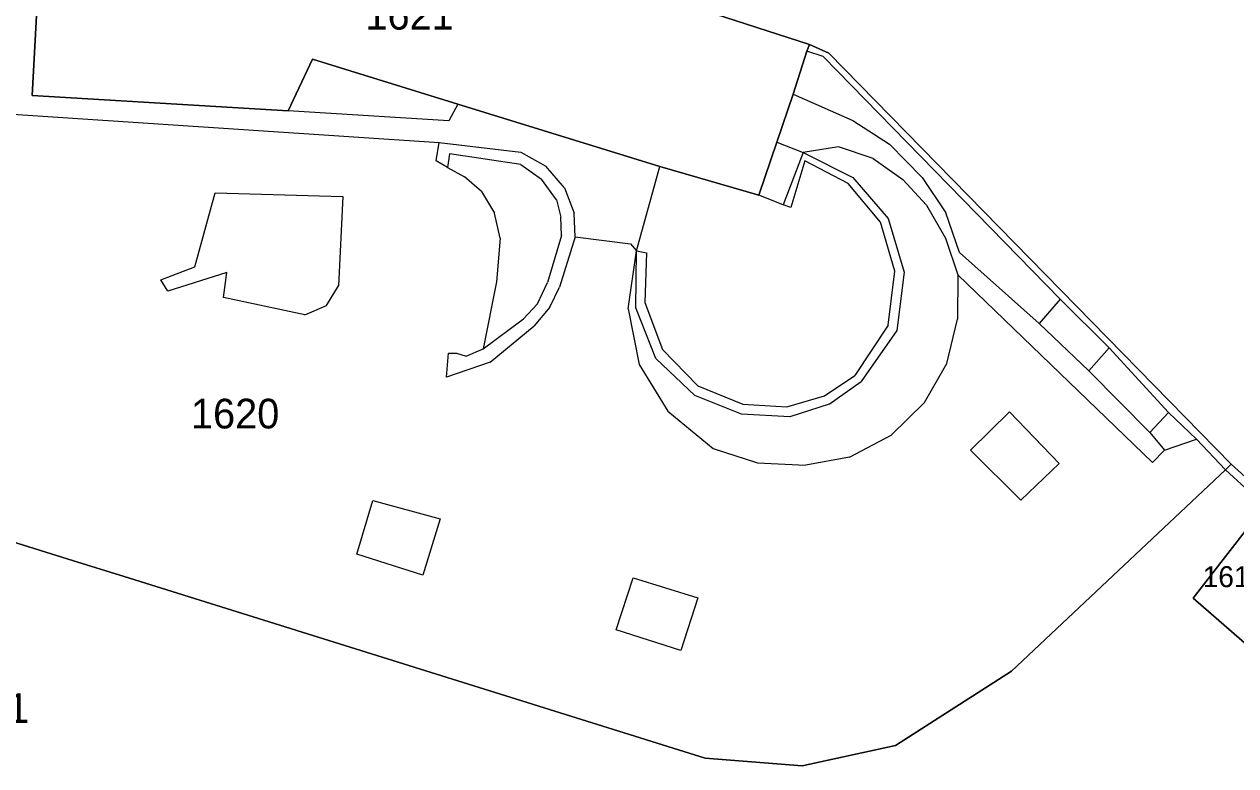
# Model space of a CAD drawing. Extents: x -598934 to -598196, y -1162208 to -1161502.
# Drawn here: x -598847.2 to -598777.9, y -1161683.9 to -1161641.4 of the extents above; entities that cross this region are included whole.
import ezdxf

# ---------------------------------------------------------------- set-up
doc = ezdxf.new("R2010")
doc.units = 0
for name, color, linetype in [('KN_CAR_KR', 7, 'Continuous'), ('KN_PARC_CIS_POZ', 7, 'Continuous'), ('KN_PARC_CIS_STAV', 7, 'Continuous'), ('KN_PARC_PLOCHA', 7, 'Continuous'), ('parcely_l', 7, 'Continuous')]:
    doc.layers.add(name, color=color, linetype=linetype)

msp = doc.modelspace()

# ---------------------------------------------------------------- linework, layer by layer
at = {"layer": 'KN_CAR_KR'}
for points in [[(-598801.51, -1161643.26), (-598802.45, -1161642.97)], [(-598787.94, -1161657.15), (-598801.51, -1161643.26)], [(-598822.41, -1161645.99), (-598822.93, -1161646.94)], [(-598803.22, -1161645.42), (-598799.8, -1161646.93)], [(-598850.77, -1161646.37), (-598823.48, -1161648.19)], [(-598822.93, -1161646.94), (-598832.12, -1161646.38)], [(-598799.8, -1161646.93), (-598797.71, -1161648.29)], [(-598804.16, -1161648.17), (-598802.66, -1161648.76)], [(-598823.65, -1161649.24), (-598823.48, -1161648.19)], [(-598823.48, -1161648.19), (-598818.8, -1161648.75)], [(-598822.88, -1161648.83), (-598823.01, -1161649.62)], [(-598818.81, -1161649.45), (-598822.88, -1161648.83)], [(-598818.8, -1161648.75), (-598817.37, -1161649.55)], [(-598802.66, -1161648.76), (-598803.79, -1161651.75)], [(-598800.63, -1161648.43), (-598802.66, -1161648.76)], [(-598802.66, -1161648.76), (-598799.8, -1161650.2)], [(-598798.65, -1161649.1), (-598800.63, -1161648.43)], [(-598795.85, -1161650.19), (-598797.71, -1161648.29)], [(-598823.01, -1161649.62), (-598823.65, -1161649.24)], [(-598818.81, -1161649.45), (-598817.62, -1161650.29)], [(-598816.3, -1161650.78), (-598817.37, -1161649.55)], [(-598802.56, -1161649.24), (-598803.36, -1161651.91)], [(-598800.07, -1161650.54), (-598802.56, -1161649.24)], [(-598798.65, -1161649.1), (-598796.95, -1161650.31)], [(-598823.01, -1161649.62), (-598822.02, -1161650.16)], [(-598821.06, -1161651), (-598822.02, -1161650.16)], [(-598812.18, -1161654.39), (-598810.86, -1161649.57)], [(-598799.8, -1161650.2), (-598797.78, -1161652.54)], [(-598795.85, -1161650.19), (-598794.49, -1161652.21)], [(-598816.76, -1161651.46), (-598817.62, -1161650.29)], [(-598816.3, -1161650.78), (-598815.76, -1161652.24)], [(-598798.23, -1161652.75), (-598800.07, -1161650.54)], [(-598795.6, -1161651.77), (-598796.95, -1161650.31)], [(-598837.46, -1161655.3), (-598836.29, -1161651.06)], [(-598836.29, -1161651.06), (-598828.99, -1161651.27)], [(-598828.99, -1161651.27), (-598829.24, -1161656.39)], [(-598821.06, -1161651), (-598820.31, -1161652.24)], [(-598816.76, -1161651.46), (-598816.51, -1161652.47)], [(-598803.79, -1161651.75), (-598805.19, -1161651.21)], [(-598819.98, -1161653.66), (-598820.31, -1161652.24)], [(-598815.7, -1161653.59), (-598815.76, -1161652.24)], [(-598803.36, -1161651.91), (-598803.79, -1161651.75)], [(-598795.6, -1161651.77), (-598794.51, -1161653.67)], [(-598793.7, -1161654.49), (-598794.49, -1161652.21)], [(-598816.48, -1161653.51), (-598816.51, -1161652.47)], [(-598797.4, -1161655.56), (-598798.23, -1161652.75)], [(-598797.78, -1161652.54), (-598796.87, -1161655.61)], [(-598819.98, -1161653.66), (-598820.19, -1161656.16)], [(-598816.48, -1161653.51), (-598817.28, -1161656.19)], [(-598815.7, -1161653.59), (-598816.6, -1161656.47)], [(-598815.7, -1161653.59), (-598812.53, -1161653.99)], [(-598794.51, -1161653.67), (-598793.81, -1161655.77)], [(-598812.66, -1161657.7), (-598812.18, -1161654.39)], [(-598812.53, -1161653.99), (-598812.18, -1161654.39)], [(-598812.23, -1161657.65), (-598812.18, -1161654.39)], [(-598812.18, -1161654.39), (-598811.62, -1161654.51)], [(-598811.62, -1161654.51), (-598811.72, -1161657.34)], [(-598793.7, -1161654.49), (-598789.14, -1161658.54)], [(-598839.4, -1161656.05), (-598837.46, -1161655.3)], [(-598835.62, -1161655.62), (-598839, -1161656.69)], [(-598835.81, -1161657.06), (-598835.62, -1161655.62)], [(-598797.78, -1161658.64), (-598797.4, -1161655.56)], [(-598796.87, -1161655.61), (-598797.3, -1161658.94)], [(-598793.81, -1161655.77), (-598793.82, -1161658.3)], [(-598793.81, -1161655.77), (-598782.67, -1161666.49)], [(-598839, -1161656.69), (-598839.4, -1161656.05)], [(-598829.93, -1161657.52), (-598829.24, -1161656.39)], [(-598820.19, -1161656.16), (-598820.96, -1161660)], [(-598817.86, -1161657.42), (-598817.28, -1161656.19)], [(-598817.14, -1161657.62), (-598816.6, -1161656.47)], [(-598831.16, -1161658.04), (-598835.81, -1161657.06)], [(-598787.94, -1161657.15), (-598789.14, -1161658.54)], [(-598785.14, -1161659.94), (-598787.94, -1161657.15)], [(-598831.16, -1161658.04), (-598829.93, -1161657.52)], [(-598817.86, -1161657.42), (-598818.65, -1161658.27)], [(-598817.14, -1161657.62), (-598818.05, -1161658.67)], [(-598812.66, -1161657.7), (-598812.03, -1161660.89)], [(-598811.09, -1161660.54), (-598812.23, -1161657.65)], [(-598811.72, -1161657.34), (-598810.7, -1161660.04)], [(-598820.96, -1161660), (-598818.65, -1161658.27)], [(-598794.44, -1161660.83), (-598793.82, -1161658.3)], [(-598789.14, -1161658.54), (-598786.31, -1161661.26)], [(-598820.56, -1161660.75), (-598818.05, -1161658.67)], [(-598797.78, -1161658.64), (-598799.7, -1161661.52)], [(-598797.3, -1161658.94), (-598799.33, -1161661.87)], [(-598785.14, -1161659.94), (-598786.31, -1161661.26)], [(-598781.74, -1161663.63), (-598785.14, -1161659.94)], [(-598823.06, -1161661.62), (-598822.95, -1161660.25)], [(-598822.95, -1161660.25), (-598822.48, -1161660.25)], [(-598822.48, -1161660.25), (-598821.93, -1161660.42)], [(-598821.93, -1161660.42), (-598820.96, -1161660)], [(-598808.85, -1161662.66), (-598811.09, -1161660.54)], [(-598810.7, -1161660.04), (-598808.68, -1161662.11)], [(-598820.56, -1161660.75), (-598823.06, -1161661.62)], [(-598812.03, -1161660.89), (-598810.39, -1161663.57)], [(-598795.7, -1161663.06), (-598794.44, -1161660.83)], [(-598786.31, -1161661.26), (-598782.82, -1161664.78)], [(-598801.44, -1161662.69), (-598799.7, -1161661.52)], [(-598801.16, -1161663.16), (-598799.33, -1161661.87)], [(-598806.18, -1161663.74), (-598808.85, -1161662.66)], [(-598808.68, -1161662.11), (-598806.11, -1161663.17)], [(-598803.59, -1161663.31), (-598801.44, -1161662.69)], [(-598806.11, -1161663.17), (-598803.59, -1161663.31)], [(-598801.16, -1161663.16), (-598803.41, -1161663.89)], [(-598797.62, -1161664.94), (-598795.7, -1161663.06)], [(-598810.39, -1161663.57), (-598807.8, -1161665.69)], [(-598803.41, -1161663.89), (-598806.18, -1161663.74)], [(-598793.07, -1161665.79), (-598790.85, -1161663.6)], [(-598790.85, -1161663.6), (-598788, -1161666.55)], [(-598782.82, -1161664.78), (-598781.74, -1161663.63)], [(-598780.15, -1161665.16), (-598781.74, -1161663.63)], [(-598782.82, -1161664.78), (-598781.98, -1161665.79)], [(-598800, -1161666.19), (-598797.62, -1161664.94)], [(-598781.98, -1161665.79), (-598780.15, -1161665.16)], [(-598780.15, -1161665.16), (-598778.49, -1161666.91)], [(-598807.8, -1161665.69), (-598805.27, -1161666.52)], [(-598800, -1161666.19), (-598802.5, -1161666.66)], [(-598790.2, -1161668.66), (-598793.07, -1161665.79)], [(-598782.67, -1161666.49), (-598781.98, -1161665.79)], [(-598805.27, -1161666.52), (-598802.5, -1161666.66)], [(-598788, -1161666.55), (-598790.2, -1161668.66)], [(-598776.24, -1161668.98), (-598778.49, -1161666.91)], [(-598828.19, -1161671.74), (-598827.27, -1161668.68)], [(-598827.27, -1161668.68), (-598823.43, -1161669.72)], [(-598823.43, -1161669.72), (-598824.41, -1161672.95)], [(-598824.41, -1161672.95), (-598828.19, -1161671.74)], [(-598813.36, -1161676.07), (-598812.38, -1161673.1)], [(-598812.38, -1161673.1), (-598808.68, -1161674.24)], [(-598808.68, -1161674.24), (-598809.65, -1161677.26)], [(-598809.65, -1161677.26), (-598813.36, -1161676.07)]]:
    msp.add_lwpolyline(points, dxfattribs=at)
at = {"layer": 'KN_PARC_PLOCHA'}
for points in [[(-598725.32, -1161626.54), (-598740.59, -1161641.59), (-598757.12, -1161657.78), (-598771.81, -1161672.37), (-598772.17, -1161671.95), (-598774.83, -1161669.62), (-598775.12, -1161669.35), (-598775.95, -1161668.6), (-598778.16, -1161666.6), (-598801.19, -1161643.07), (-598802.29, -1161642.59), (-598825.81, -1161634.98)], [(-598850.21, -1161635.93), (-598847.12, -1161635.94), (-598846.25, -1161636), (-598846.76, -1161645.5), (-598832.12, -1161646.38), (-598830.73, -1161643.42), (-598822.41, -1161645.99), (-598810.86, -1161649.57), (-598805.19, -1161651.21), (-598804.16, -1161648.17), (-598803.22, -1161645.42), (-598802.45, -1161642.97), (-598802.29, -1161642.59), (-598801.19, -1161643.07), (-598778.16, -1161666.6), (-598778.49, -1161666.91), (-598790.74, -1161678.44), (-598797.36, -1161682.69), (-598802.7, -1161683.85), (-598808.26, -1161683.41), (-598841.51, -1161673.02), (-598844.45, -1161672.1), (-598874.24, -1161662.79)], [(-598874.24, -1161662.79), (-598844.45, -1161672.1), (-598841.51, -1161673.02), (-598808.26, -1161683.41), (-598802.7, -1161683.85), (-598797.36, -1161682.69), (-598790.74, -1161678.44), (-598778.49, -1161666.91), (-598778.16, -1161666.6), (-598775.95, -1161668.6)], [(-598776.24, -1161668.98), (-598780.33, -1161674.26), (-598770.1, -1161683.17)]]:
    msp.add_lwpolyline(points, dxfattribs=at)
for points in [[(-598826.13, -1161634.76), (-598825.81, -1161634.98), (-598802.29, -1161642.59), (-598802.45, -1161642.97), (-598803.22, -1161645.42), (-598804.16, -1161648.17), (-598805.19, -1161651.21), (-598810.86, -1161649.57), (-598822.41, -1161645.99), (-598830.73, -1161643.42), (-598832.12, -1161646.38), (-598846.76, -1161645.5), (-598846.25, -1161636), (-598837.22, -1161636.47), (-598834.02, -1161636.65), (-598829.78, -1161636.87), (-598828.54, -1161634.07)], [(-598771.81, -1161672.37), (-598772.15, -1161672.73), (-598773.46, -1161673.93), (-598773.92, -1161674.54), (-598776.43, -1161677.01), (-598772.19, -1161681.29), (-598769.56, -1161678.91), (-598767.8, -1161680.81), (-598770.1, -1161683.17), (-598780.33, -1161674.26), (-598776.24, -1161668.98), (-598775.95, -1161668.6), (-598775.12, -1161669.35), (-598774.83, -1161669.62), (-598772.17, -1161671.95)]]:
    msp.add_lwpolyline(points, close=True, dxfattribs=at)
at = {"layer": 'parcely_l'}
for points in [[(-598826.13, -1161634.76), (-598825.81, -1161634.98), (-598802.29, -1161642.59)], [(-598778.16, -1161666.6), (-598778.49, -1161666.91), (-598790.74, -1161678.44), (-598797.36, -1161682.69), (-598802.7, -1161683.85), (-598808.26, -1161683.41), (-598841.51, -1161673.02), (-598844.45, -1161672.1), (-598874.24, -1161662.79), (-598863.67, -1161643.85), (-598862.92, -1161642.5), (-598858.75, -1161635.43), (-598850.21, -1161635.93), (-598847.12, -1161635.94), (-598846.25, -1161636)], [(-598846.25, -1161636), (-598846.76, -1161645.5), (-598832.12, -1161646.38), (-598830.73, -1161643.42), (-598822.41, -1161645.99), (-598810.86, -1161649.57), (-598805.19, -1161651.21), (-598804.16, -1161648.17), (-598803.22, -1161645.42), (-598802.45, -1161642.97), (-598802.29, -1161642.59)], [(-598802.29, -1161642.59), (-598801.19, -1161643.07), (-598778.16, -1161666.6)], [(-598778.16, -1161666.6), (-598775.95, -1161668.6)], [(-598775.95, -1161668.6), (-598776.24, -1161668.98), (-598780.33, -1161674.26), (-598770.1, -1161683.17)]]:
    msp.add_lwpolyline(points, dxfattribs=at)

# ---------------------------------------------------------------- texts
at = {"layer": 'KN_PARC_CIS_POZ'}
for s, height, p in [('1619/9', 1.2, (-598779.79, -1161673.63)), ('1619/1', 1.7, (-598853.887, -1161681.4))]:
    msp.add_text(s, height=height, dxfattribs=at).set_placement(p)
at = {"layer": 'KN_PARC_CIS_STAV'}
for s, p in [('1621', (-598827.702, -1161641.73)), ('1620', (-598837.682, -1161664.55))]:
    msp.add_text(s, height=1.7, dxfattribs=at).set_placement(p)

doc.saveas('drawing.dxf')
